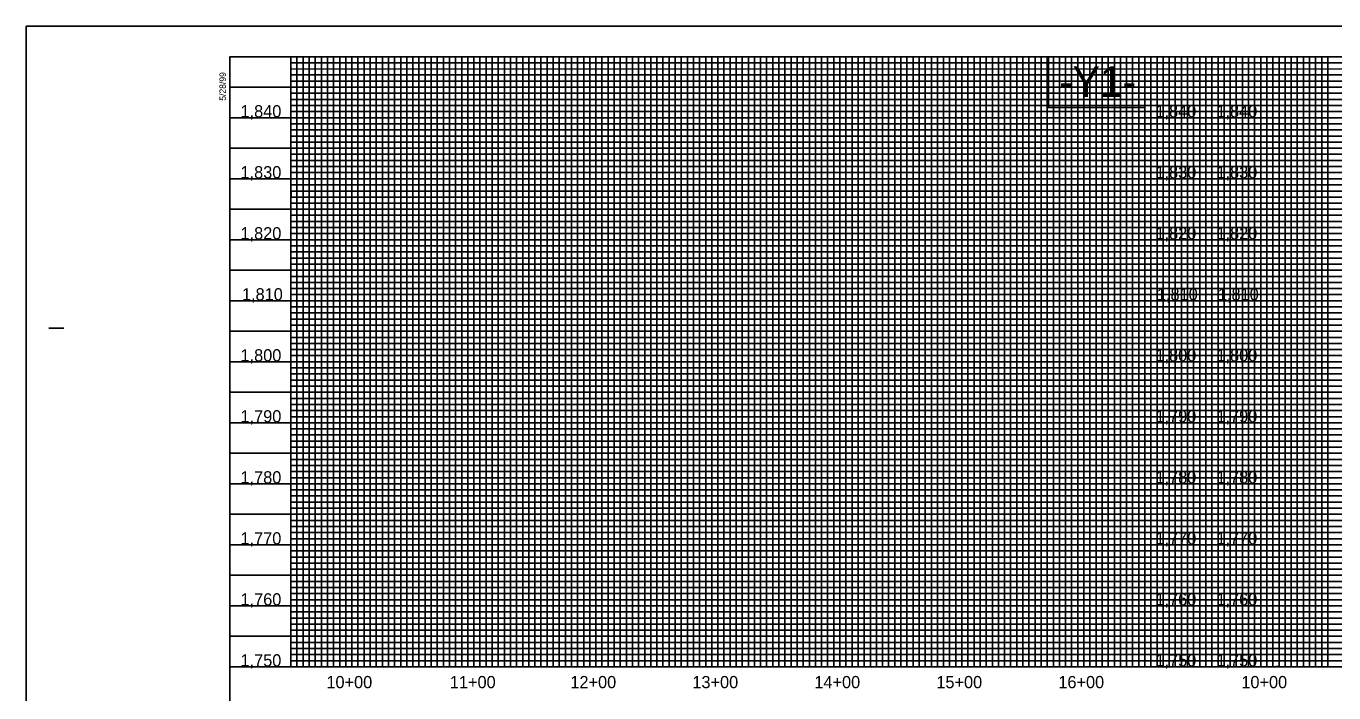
# Model space of a CAD drawing. Extents: x 505602 to 507705, y 483109 to 484209.
# Drawn here: x 505602 to 506674, y 483662 to 484209 of the extents above; entities that cross this region are included whole.
import ezdxf

# ---------------------------------------------------------------- set-up
doc = ezdxf.new("R2010")
doc.units = 0
for name, color, linetype in [('Exist Vertical Profile Vertical Axis Label', 7, 'Continuous'), ('Old_Level_1', 7, 'Continuous'), ('Prop Grid Mask', 7, 'Continuous'), ('Sheet Layout Profile Border Port 1', 7, 'Continuous'), ('Sheet Plot Border Outside CELL', 7, 'Continuous'), ('Sheet Profile CELL', 7, 'Continuous'), ('Sheet Profile Grid Major CELL', 7, 'Continuous'), ('Sheet Profile Grid Middle CELL', 7, 'Continuous'), ('Sheet Profile Grid Minor CELL', 7, 'Continuous')]:
    doc.layers.add(name, color=color, linetype=linetype)

msp = doc.modelspace()

# ---------------------------------------------------------------- linework, layer by layer
at = {"layer": 'Prop Grid Mask'}
msp.add_lwpolyline([(506519.1, 484183.7), (506440.1, 484183.7), (506440.1, 484142), (506519.1, 484142)], close=True, dxfattribs=at)
at = {"layer": 'Sheet Layout Profile Border Port 1'}
for points in [[(505819.1, 484183.7), (506519.1, 484183.7), (506519.1, 483683.7), (505819.1, 483683.7)], [(506619.1, 484183.7), (506619.1, 483683.7), (507219.1, 483684), (507219.1, 484022.7), (507069.1, 484022.7), (507069, 484183.7)]]:
    msp.add_lwpolyline(points, close=True, dxfattribs=at)
at = {"layer": 'Sheet Plot Border Outside CELL'}
msp.add_lwpolyline([(505602.1, 483108.7), (507286.1, 483108.7), (507286.1, 484208.7), (505602.1, 484208.7)], close=True, dxfattribs=at)
at = {"layer": 'Sheet Profile CELL'}
for p, q in [((506569.1, 483683.7), (506569.1, 484183.7)), ((505620.6, 483961.2), (505633.1, 483961.2)), ((505769.1, 483683.7), (507269.1, 483683.7))]:
    msp.add_line(p, q, dxfattribs=at)
msp.add_lwpolyline([(507269.1, 484183.7), (505769.1, 484183.7), (505769.1, 483133.7), (507269.1, 483133.7)], close=True, dxfattribs=at)
at = {"layer": 'Sheet Profile Grid Major CELL'}
for points in [[(505819.1, 484183.7), (505819.1, 483683.7), (505869.1, 483683.7), (505869.1, 484183.7), (505919.1, 484183.7), (505919.1, 483683.7), (505969.1, 483683.7), (505969.1, 484183.7), (506019.1, 484183.7), (506019.1, 483683.7), (506069.1, 483683.7), (506069.1, 484183.7), (506119.1, 484183.7), (506119.1, 483683.7), (506169.1, 483683.7), (506169.1, 484183.7), (506219.1, 484183.7), (506219.1, 483683.7), (506269.1, 483683.7), (506269.1, 484183.7), (506319.1, 484183.7), (506319.1, 483683.7), (506369.1, 483683.7), (506369.1, 484183.7), (506419.1, 484183.7), (506419.1, 483683.7), (506469.1, 483683.7), (506469.1, 484183.7), (506519.1, 484183.7), (506519.1, 483683.7), (506569.1, 483683.7), (506569.1, 484183.7), (506619.1, 484183.7), (506619.1, 483683.7), (506669.1, 483683.7), (506669.1, 484183.7), (506719.1, 484183.7)], [(505769.1, 484133.7), (507069.1, 484133.7)], [(507069.1, 484083.7), (505769.1, 484083.7), (505769.1, 484033.7), (507069.1, 484033.7)], [(507269.1, 483983.7), (505769.1, 483983.7), (505769.1, 483933.7), (507269.1, 483933.7)], [(507269.1, 483883.7), (505769.1, 483883.7), (505769.1, 483833.7), (507269.1, 483833.7)], [(507269.1, 483783.7), (505769.1, 483783.7), (505769.1, 483783.7), (505769.1, 483733.7), (507269.1, 483733.7)]]:
    msp.add_lwpolyline(points, dxfattribs=at)
at = {"layer": 'Sheet Profile Grid Middle CELL'}
msp.add_line((505769.1, 484158.7), (507069, 484158.7), dxfattribs=at)
msp.add_line((505769.1, 484158.7), (507069, 484158.7), dxfattribs=at)
for points in [[(505844.1, 484183.7), (505844.1, 483683.7), (505894.1, 483683.7), (505894.1, 484183.7), (505944.1, 484183.7), (505944.1, 483683.7), (505994.1, 483683.7), (505994.1, 484183.7), (506044.1, 484183.7), (506044.1, 483683.7), (506094.1, 483683.7), (506094.1, 484183.7), (506144.1, 484183.7), (506144.1, 483683.7), (506194.1, 483683.7), (506194.1, 484183.7), (506244.1, 484183.7), (506244.1, 483683.7), (506294.1, 483683.7), (506294.1, 484183.7), (506344.1, 484183.7), (506344.1, 483683.7), (506394.1, 483683.7), (506394.1, 483683.7), (506394.1, 484183.7), (506444.1, 484183.7), (506444.1, 483683.7), (506494.1, 483683.7), (506494.1, 484183.7), (506544.1, 484183.7), (506544.1, 483683.7), (506594.1, 483683.7), (506594.1, 484183.7), (506644.1, 484183.7), (506644.1, 483683.7), (506694.1, 483683.7)], [(507069.1, 484108.7), (505769.1, 484108.7), (505769.1, 484058.7), (507069.1, 484058.7)], [(507269.1, 484008.7), (505769.1, 484008.7), (505769.1, 483958.7), (507094.1, 483958.7)], [(507269.1, 483908.7), (505769.1, 483908.7), (505769.1, 483858.7), (507269.1, 483858.7)], [(507269.1, 483808.7), (505769.1, 483808.7), (505769.1, 483758.7), (507269.1, 483758.7)], [(507269.1, 483708.7), (505769.1, 483708.7)]]:
    msp.add_lwpolyline(points, dxfattribs=at)
at = {"layer": 'Sheet Profile Grid Minor CELL'}
for p, q in [((505819.1, 484178.7), (507069.1, 484178.7)), ((505819.1, 484173.7), (505819.1, 484173.7)), ((507069.1, 484173.7), (505819.1, 484173.4)), ((505819.1, 484168.7), (507069.1, 484168.7)), ((507069, 484048.7), (505819.1, 484048.7)), ((507069.1, 484043.7), (505819.1, 484043.7)), ((507069.1, 484038.7), (505819.1, 484038.7)), ((505819.1, 484028.7), (507069.1, 484028.7)), ((507069.1, 484023.7), (505819.1, 484023.7)), ((505819.1, 484018.7), (507219.1, 484018.7)), ((507219.1, 483998.7), (505819.1, 483998.7)), ((505819.1, 483993.7), (507219.1, 483993.7)), ((507219.1, 483973.7), (505819.1, 483973.7)), ((505819.1, 483968.7), (507219.1, 483968.7)), ((507219.1, 483948.7), (505819.1, 483948.7)), ((505819.1, 483943.7), (507219.1, 483943.7)), ((507219.1, 483938.7), (505819.1, 483938.7)), ((505819.1, 483928.7), (507219.1, 483928.7)), ((507219.1, 483923.7), (505819.1, 483923.7)), ((505819.1, 483918.7), (507219.1, 483918.7)), ((507219.1, 483913.7), (505819.1, 483913.7)), ((505819.1, 483903.7), (507219.1, 483903.7)), ((507219.1, 483898.7), (505819.1, 483898.7)), ((505819.1, 483893.7), (507219.1, 483893.7)), ((507219.1, 483888.7), (505819.1, 483888.7)), ((505819.1, 483878.7), (507219.1, 483878.7)), ((507219.1, 483873.7), (505819.1, 483873.7)), ((505819.1, 483868.7), (507219.1, 483868.7)), ((507219.1, 483863.7), (505819.1, 483863.7)), ((505819.1, 483853.7), (507219.1, 483853.7)), ((507219.1, 483848.7), (505819.1, 483848.7)), ((505819.1, 483843.7), (507219.1, 483843.7)), ((507219.1, 483838.7), (505819.1, 483838.7)), ((505819.1, 483828.7), (507219.1, 483828.7)), ((507219.1, 483823.7), (505819.1, 483823.7)), ((505819.1, 483818.7), (507219.1, 483818.7)), ((507219.1, 483813.7), (505819.1, 483813.7)), ((505819.1, 483803.7), (507219.1, 483803.7)), ((507219.1, 483798.7), (505819.1, 483798.7)), ((507219.1, 483793.7), (505819.1, 483793.7)), ((507219.1, 483788.7), (505819.1, 483788.7)), ((505819.1, 483778.7), (507219.1, 483778.7)), ((507219.1, 483773.7), (505819.1, 483773.7)), ((505819.1, 483768.7), (507219.1, 483768.7)), ((507219.1, 483763.7), (505819.1, 483763.7)), ((505819.1, 483753.7), (507219.1, 483753.7)), ((507219.1, 483748.7), (505819.1, 483748.7)), ((505819.1, 483743.7), (507219.1, 483743.7)), ((507219.1, 483738.7), (505819.1, 483738.7)), ((505819.1, 483728.7), (507219.1, 483728.7)), ((507219.1, 483723.7), (505819.1, 483723.7)), ((505819.1, 483718.7), (507219.1, 483718.7)), ((507219.1, 483713.7), (505819.1, 483713.7)), ((505819.1, 483703.7), (507219.1, 483703.7)), ((507219.1, 483698.7), (505819.1, 483698.7)), ((505819.1, 483693.7), (507219.1, 483693.7))]:
    msp.add_line(p, q, dxfattribs=at)
for points in [[(505824.1, 484183.7), (505824.1, 483683.7), (505829.1, 483683.7), (505829.1, 484183.7), (505834.1, 484183.7), (505834.1, 483683.7), (505839.1, 483683.7), (505839.1, 484183.7), (505849.1, 484183.7), (505849.1, 483683.7), (505854.1, 483683.7), (505854.1, 484183.7), (505859.1, 484183.7), (505859.1, 483683.7), (505864.1, 483683.7), (505874.1, 483683.7), (505879.1, 483683.7), (505879.1, 484183.7), (505884.1, 484183.7), (505884.1, 483683.7), (505889.1, 483683.7), (505889.1, 484183.7), (505899.1, 484183.7), (505899.1, 483683.7), (505904.1, 483683.7), (505904.1, 484183.7), (505909.1, 484183.7), (505909.1, 483683.7), (505914.1, 483683.7), (505914.1, 484183.7), (505924.1, 484183.7), (505924.1, 483683.7), (505929.1, 483683.7), (505929.1, 484183.7), (505934.1, 484183.7), (505934.1, 483683.7), (505939.1, 483683.7), (505939.1, 484183.7), (505949.1, 484183.7), (505949.1, 483683.7), (505954.1, 483683.7), (505954.1, 484183.7), (505959.1, 484183.7), (505959.1, 483683.7), (505964.1, 483683.7), (505964.1, 484183.7), (505974.1, 484183.7), (505974.1, 483683.7), (505979.1, 483683.7), (505979.1, 484183.7), (505984.1, 484183.7), (505984.1, 483683.7), (505989.1, 483683.7), (505989.1, 484183.7), (505999.1, 484183.7), (505999.1, 483683.7), (506004.1, 483683.7), (506004.1, 484183.7), (506009.1, 484183.7), (506009.1, 483683.7), (506014.1, 483683.7), (506014.1, 484183.7), (506024.1, 484183.7), (506024.1, 483683.7), (506029.1, 483683.7), (506029.1, 484183.7), (506034.1, 484183.7), (506034.1, 483683.7)], [(505864.1, 483683.7), (505864.1, 484183.7), (505874.1, 484183.7), (505874.1, 483683.7)], [(506034.1, 483683.7), (506039.1, 483683.7), (506039.1, 484183.7), (506049.1, 484183.7), (506049.1, 483683.7), (506054.1, 483683.7), (506054.1, 484183.7), (506059.1, 484183.7), (506059.1, 483683.7), (506064.1, 483683.7), (506064.1, 484183.7), (506074.1, 484183.7), (506074.1, 483683.7), (506079.1, 483683.7), (506079.1, 484183.7), (506084.1, 484183.7), (506084.1, 483683.7), (506089.1, 483683.7), (506089.1, 484183.7), (506099.1, 484183.7), (506099.1, 483683.7), (506104.1, 483683.7), (506104.1, 484183.7), (506109.1, 484183.7), (506109.1, 483683.7), (506114.1, 483683.7), (506114.1, 484183.7), (506124.1, 484183.7), (506124.1, 483683.7), (506129.1, 483683.7), (506129.1, 484183.7), (506134.1, 484183.7), (506134.1, 483683.7), (506139.1, 483683.7), (506139.1, 484183.7), (506149.1, 484183.7), (506149.1, 483683.7), (506154.1, 483683.7), (506154.1, 484183.7), (506159.1, 484183.7), (506159.1, 483683.7), (506164.1, 483683.7), (506164.1, 484183.7), (506174.1, 484183.7), (506174.1, 483683.7), (506179.1, 483683.7), (506179.1, 484183.7), (506184.1, 484183.7), (506184.1, 483683.7), (506189.1, 483683.7), (506189.1, 484183.7), (506199.1, 484183.7), (506199.1, 483683.7), (506204.1, 483683.7), (506204.1, 484183.7), (506209.1, 484183.7), (506209.1, 483683.7), (506214.1, 483683.7), (506214.1, 484183.7), (506224.1, 484183.7), (506224.1, 483683.7), (506229.1, 483683.7), (506229.1, 484183.7), (506234.1, 484183.7), (506234.1, 483683.7), (506239.1, 483683.7), (506239.1, 484183.7), (506249.1, 484183.7), (506249.1, 483683.7), (506254.1, 483683.7), (506254.1, 484183.7), (506259.1, 484183.7), (506259.1, 483683.7), (506264.1, 483683.7), (506264.1, 484183.7), (506274.1, 484183.7), (506274.1, 483683.7), (506279.1, 483683.7), (506279.1, 484183.7), (506284.1, 484183.7), (506284.1, 483683.7), (506289.1, 483683.7), (506289.1, 484183.7), (506299.1, 484183.7), (506299.1, 483683.7), (506304.1, 483683.7), (506304.1, 484183.7), (506309.1, 484183.7), (506309.1, 483683.7), (506314.1, 483683.7), (506314.1, 484183.7), (506324.1, 484183.7), (506324.1, 483683.7), (506329.1, 483683.7), (506329.1, 484183.7), (506334.1, 484183.7), (506334.1, 483683.7), (506339.1, 483683.7), (506339.1, 484183.7), (506349.1, 484183.7)], [(506349.1, 484183.7), (506349.1, 483683.7), (506354.1, 483683.7), (506354.1, 484183.7), (506359.1, 484183.7), (506359.1, 483683.7), (506364.1, 483683.7), (506364.1, 484183.7), (506374.1, 484183.7), (506374.1, 483683.7), (506379.1, 483683.7), (506379.1, 484183.7), (506384.1, 484183.7), (506384.1, 483683.7), (506389.1, 483683.7), (506389.1, 484183.7), (506399.1, 484183.7), (506399.1, 483683.7), (506404.1, 483683.7), (506404.1, 484183.7), (506409.1, 484183.7), (506409.1, 483683.7), (506414.1, 483683.7), (506414.1, 484183.7), (506424.1, 484183.7), (506424.1, 483683.7), (506429.1, 483683.7), (506429.1, 484183.7), (506434.1, 484183.7), (506434.1, 483683.7), (506439.1, 483683.7), (506439.1, 484183.7), (506449.1, 484183.7), (506449.1, 483683.7), (506454.1, 483683.7), (506454.1, 484183.7), (506459.1, 484183.7), (506459.1, 483683.7), (506464.1, 483683.7), (506464.1, 484183.7), (506474.1, 484183.7), (506474.1, 483683.7), (506474.1, 483683.7), (506479.1, 483683.7), (506479.1, 484183.7), (506484.1, 484183.7), (506484.1, 483683.7), (506489.1, 483683.7), (506489.1, 484183.7), (506499.1, 484183.7), (506499.1, 483683.7), (506504.1, 483683.7), (506504.1, 484183.7), (506509.1, 484183.7), (506509.1, 483683.7), (506514.1, 483683.7), (506514.1, 484183.7), (506524.1, 484183.7), (506524.1, 483683.7), (506529.1, 483683.7), (506529.1, 484183.7), (506534.1, 484183.7), (506534.1, 483683.7), (506539.1, 483683.7), (506539.1, 484183.7), (506549.1, 484183.7), (506549.1, 483683.7), (506554.1, 483683.7), (506554.1, 484183.7), (506559.1, 484183.7), (506559.1, 483683.7), (506564.1, 483683.7), (506564.1, 484183.7), (506574.1, 484183.7), (506574.1, 483683.7), (506579.1, 483683.7), (506579.1, 484183.7), (506584.1, 484183.7), (506584.1, 483683.7), (506589.1, 483683.7), (506589.1, 484183.7), (506599.1, 484183.7), (506599.1, 483683.7), (506604.1, 483683.7), (506604.1, 484183.7), (506609.1, 484183.7), (506609.1, 483683.7), (506614.1, 483683.7), (506614.1, 484183.7), (506624.1, 484183.7), (506624.1, 483683.7), (506628.8, 483684.3), (506629.1, 483683.7), (506629.1, 484183.7), (506634.1, 484183.7), (506634.1, 483683.7), (506639.1, 483683.7), (506639.1, 484183.7), (506649.1, 484183.7), (506649.1, 483683.7), (506654.1, 483683.7)], [(506654.1, 483683.7), (506654.1, 484183.7), (506659.1, 484183.7), (506659.1, 483683.7), (506664.1, 483683.7), (506664.1, 484183.7), (506674.1, 484183.7)], [(507069.1, 484163.7), (505819.1, 484163.7), (505819.1, 484153.7), (507069.1, 484153.7)], [(507069, 484148.7), (505819.1, 484148.7), (505819.1, 484143.7), (507069.1, 484143.7)], [(507069.1, 484138.7), (505819.1, 484138.7), (505819.1, 484128.7), (507069.1, 484128.7)], [(507069.1, 484123.7), (505819.1, 484123.7), (505819.1, 484118.7), (507069.1, 484118.7)], [(507069.1, 484113.7), (505819.1, 484113.7), (505819.1, 484103.7), (507069.1, 484103.7)], [(507069.1, 484098.7), (505819.1, 484098.7), (505819.1, 484093.7), (507069.1, 484093.7)], [(507069.1, 484088.7), (505819.1, 484088.7), (505819.1, 484078.7), (507069.1, 484078.7)], [(507069.1, 484073.6), (505819.2, 484073.6), (505819.2, 484068.7), (507069.1, 484068.7)], [(507069.1, 484063.7), (505819.1, 484063.7), (505819.1, 484053.7), (507069.1, 484053.7)], [(507219.1, 484013.7), (505819.1, 484013.7), (505819.1, 484003.7), (507219.1, 484003.7)], [(507219.1, 483988.7), (505819.1, 483988.7), (505819.1, 483978.7), (507219.1, 483978.7)], [(507219.1, 483963.7), (505819.1, 483963.7), (505819.1, 483953.7), (507219.1, 483953.7)], [(507219.1, 483688.7), (505819.1, 483688.7)]]:
    msp.add_lwpolyline(points, dxfattribs=at)

# ---------------------------------------------------------------- texts
at = {"layer": 'Exist Vertical Profile Vertical Axis Label'}
for s, p in [('1,840', (505777.8, 484134)), ('1,840', (506527.8, 484134)), ('1,840', (506577.8, 484134)), ('1,830', (505777.8, 484084)), ('1,830', (506527.8, 484084)), ('1,830', (506577.8, 484084)), ('1,820', (505777.8, 484034)), ('1,820', (506527.8, 484034)), ('1,820', (506577.8, 484034)), ('1,810', (505779, 483984)), ('1,810', (506529, 483984)), ('1,810', (506579, 483984)), ('1,800', (505777.8, 483934)), ('1,800', (506527.8, 483934)), ('1,800', (506577.8, 483934)), ('1,790', (505777.8, 483884)), ('1,790', (506527.8, 483884)), ('1,790', (506577.8, 483884)), ('1,780', (505777.8, 483834)), ('1,780', (506527.8, 483834)), ('1,780', (506577.8, 483834)), ('1,770', (505777.8, 483784)), ('1,770', (506527.8, 483784)), ('1,770', (506577.8, 483784)), ('1,760', (505777.8, 483734)), ('1,760', (506527.8, 483734)), ('1,760', (506577.8, 483734)), ('1,750', (505777.8, 483684)), ('1,750', (506527.8, 483684)), ('1,750', (506577.8, 483684)), ('10+00', (505848.2, 483666.2)), ('11+00', (505949.4, 483666.2)), ('12+00', (506048.2, 483666.2)), ('13+00', (506148.2, 483666.2)), ('14+00', (506248.2, 483666.2)), ('15+00', (506348.2, 483666.2)), ('16+00', (506448.2, 483666.2)), ('10+00', (506598.2, 483666.2))]:
    msp.add_text(s, height=10, dxfattribs=at).set_placement(p)
at = {"layer": 'Old_Level_1'}
msp.add_text('-Y1-', height=25, dxfattribs=at).set_placement((506448.8, 484150.7))
at = {"layer": 'Sheet Profile CELL'}
msp.add_text('5/28/99', height=5.25, rotation=90, dxfattribs=at).set_placement((505765.8, 484147.6))

doc.saveas('drawing.dxf')
